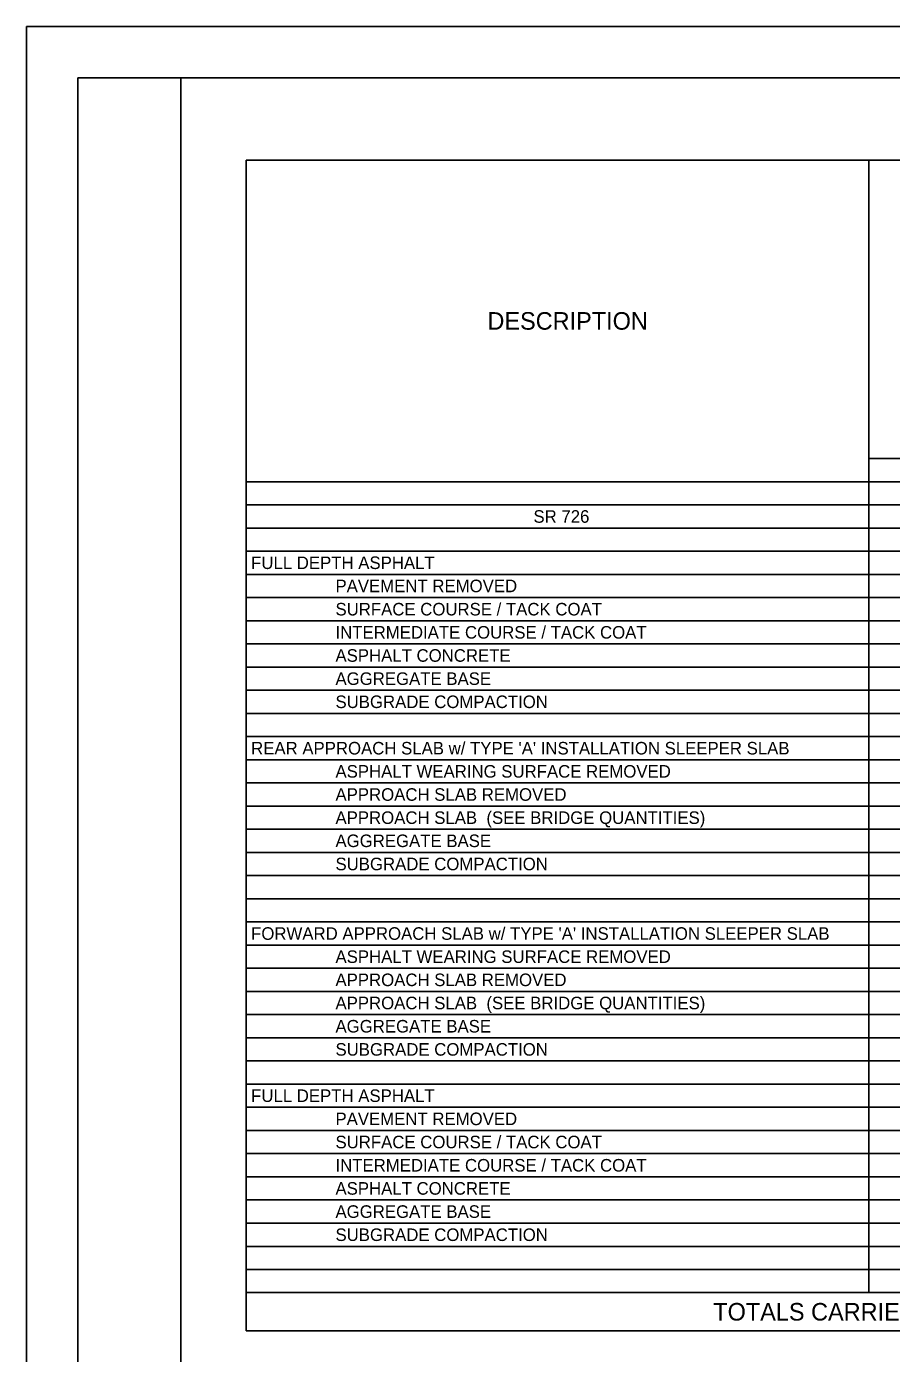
# Model space of a CAD drawing. Extents: x 0 to 34, y 0 to 22.
# Drawn here: x 0 to 8.41, y 9.11 to 22 of the extents above; entities that cross this region are included whole.
import ezdxf

# ---------------------------------------------------------------- set-up
doc = ezdxf.new("R2010")
doc.units = 0
for name, color, linetype in [('SH_Border', 7, 'Continuous'), ('SH_Cut_Line', 7, 'Continuous'), ('SH_Text', 7, 'Continuous')]:
    doc.layers.add(name, color=color, linetype=linetype)

msp = doc.modelspace()

# ---------------------------------------------------------------- linework, layer by layer
at = {"layer": 'SH_Border'}
for points in [[(0.5, 21.5), (1.5, 21.5), (1.5, 0.5), (0.5, 0.5)], [(1.5, 21.5), (33.5, 21.5), (33.5, 0.5), (1.5, 0.5)]]:
    msp.add_lwpolyline(points, close=True, dxfattribs=at)
at = {"layer": 'SH_Cut_Line'}
msp.add_lwpolyline([(0, 0), (34, 0), (34, 22), (0, 22)], close=True, dxfattribs=at)
at = {"layer": 'SH_Text'}
for p, q in [((2.135, 20.703), (22.576, 20.703)), ((2.135, 20.703), (2.135, 9.325)), ((8.186, 20.703), (8.186, 9.696)), ((8.186, 17.802), (22.576, 17.802)), ((2.135, 17.577), (22.576, 17.577)), ((2.135, 17.352), (22.576, 17.352)), ((2.135, 17.126), (22.576, 17.126)), ((2.135, 16.901), (22.576, 16.901)), ((2.135, 16.676), (22.576, 16.676)), ((2.135, 16.451), (22.576, 16.451)), ((2.135, 16.226), (22.576, 16.226)), ((2.135, 16.001), (22.576, 16.001)), ((2.135, 15.775), (22.576, 15.775)), ((2.135, 15.55), (22.576, 15.55)), ((2.135, 15.325), (22.576, 15.325)), ((2.135, 15.1), (22.576, 15.1)), ((2.135, 14.875), (22.576, 14.875)), ((2.135, 14.65), (22.576, 14.65)), ((2.135, 14.424), (22.576, 14.424)), ((2.135, 14.199), (22.576, 14.199)), ((2.135, 13.974), (22.576, 13.974)), ((2.135, 13.749), (22.576, 13.749)), ((2.135, 13.524), (22.576, 13.524)), ((2.135, 13.299), (22.576, 13.299)), ((2.135, 13.073), (22.576, 13.073)), ((2.135, 12.848), (22.576, 12.848)), ((2.135, 12.623), (22.576, 12.623)), ((2.135, 12.398), (22.576, 12.398)), ((2.135, 12.173), (22.576, 12.173)), ((2.135, 11.948), (22.576, 11.948)), ((2.135, 11.722), (22.576, 11.722)), ((2.135, 11.497), (22.576, 11.497)), ((2.135, 11.272), (22.576, 11.272)), ((2.135, 11.047), (22.576, 11.047)), ((2.135, 10.822), (22.576, 10.822)), ((2.135, 10.597), (22.576, 10.597)), ((2.135, 10.371), (22.576, 10.371)), ((2.135, 10.146), (22.576, 10.146)), ((2.135, 9.921), (22.576, 9.921)), ((2.135, 9.696), (22.576, 9.696)), ((2.135, 9.325), (22.576, 9.325))]:
    msp.add_line(p, q, dxfattribs=at)
for points in [[(2.135, 20.703), (2.954, 20.703), (2.954, 20.703), (2.135, 20.703)], [(2.135, 20.703), (7.367, 20.703), (7.367, 20.703), (2.135, 20.703)], [(2.135, 20.703), (3.284, 20.703), (3.284, 20.703), (2.135, 20.703)], [(2.135, 20.703), (3.284, 20.703), (3.284, 20.703), (2.135, 20.703)], [(2.135, 20.703), (3.1, 20.703), (3.1, 20.703), (2.135, 20.703)], [(2.135, 20.703), (3.1, 20.703), (3.1, 20.703), (2.135, 20.703)], [(2.135, 20.703), (3.1, 20.703), (3.1, 20.703), (2.135, 20.703)], [(2.135, 20.703), (3.1, 20.703), (3.1, 20.703), (2.135, 20.703)], [(2.135, 20.703), (3.1, 20.703), (3.1, 20.703), (2.135, 20.703)], [(2.135, 20.703), (2.868, 20.703), (2.868, 20.703), (2.135, 20.703)], [(2.135, 20.703), (2.868, 20.703), (2.868, 20.703), (2.135, 20.703)], [(2.135, 20.703), (2.868, 20.703), (2.868, 20.703), (2.135, 20.703)], [(2.135, 20.703), (2.868, 20.703), (2.868, 20.703), (2.135, 20.703)], [(2.135, 20.703), (3.052, 20.703), (3.052, 20.703), (2.135, 20.703)], [(2.135, 20.703), (2.905, 20.703), (2.905, 20.703), (2.135, 20.703)], [(2.135, 20.703), (2.893, 20.703), (2.893, 20.703), (2.135, 20.703)], [(2.135, 20.703), (3.1, 20.703), (3.1, 20.703), (2.135, 20.703)], [(2.135, 20.703), (3.052, 20.703), (3.052, 20.703), (2.135, 20.703)], [(2.135, 20.703), (2.954, 20.703), (2.954, 20.703), (2.135, 20.703)], [(2.135, 20.703), (7.367, 20.703), (7.367, 20.703), (2.135, 20.703)], [(2.135, 20.703), (3.284, 20.703), (3.284, 20.703), (2.135, 20.703)], [(2.135, 20.703), (3.284, 20.703), (3.284, 20.703), (2.135, 20.703)], [(2.135, 20.703), (3.1, 20.703), (3.1, 20.703), (2.135, 20.703)], [(2.135, 20.703), (3.1, 20.703), (3.1, 20.703), (2.135, 20.703)], [(2.135, 20.703), (3.1, 20.703), (3.1, 20.703), (2.135, 20.703)], [(2.135, 20.703), (3.1, 20.703), (3.1, 20.703), (2.135, 20.703)], [(2.135, 20.703), (3.1, 20.703), (3.1, 20.703), (2.135, 20.703)], [(2.135, 20.703), (2.868, 20.703), (2.868, 20.703), (2.135, 20.703)], [(2.135, 20.703), (2.868, 20.703), (2.868, 20.703), (2.135, 20.703)], [(2.135, 20.703), (2.868, 20.703), (2.868, 20.703), (2.135, 20.703)], [(2.135, 20.703), (2.868, 20.703), (2.868, 20.703), (2.135, 20.703)], [(2.135, 20.703), (3.052, 20.703), (3.052, 20.703), (2.135, 20.703)], [(2.135, 20.703), (2.905, 20.703), (2.905, 20.703), (2.135, 20.703)], [(2.135, 20.703), (2.893, 20.703), (2.893, 20.703), (2.135, 20.703)], [(2.135, 20.703), (3.1, 20.703), (3.1, 20.703), (2.135, 20.703)], [(2.135, 20.703), (3.052, 20.703), (3.052, 20.703), (2.135, 20.703)], [(2.135, 20.703), (2.954, 20.703), (2.954, 20.703), (2.135, 20.703)], [(2.135, 20.703), (7.367, 20.703), (7.367, 20.703), (2.135, 20.703)], [(2.135, 20.703), (3.284, 20.703), (3.284, 20.703), (2.135, 20.703)], [(2.135, 20.703), (3.284, 20.703), (3.284, 20.703), (2.135, 20.703)], [(2.135, 20.703), (3.1, 20.703), (3.1, 20.703), (2.135, 20.703)], [(2.135, 20.703), (3.1, 20.703), (3.1, 20.703), (2.135, 20.703)], [(2.135, 20.703), (3.1, 20.703), (3.1, 20.703), (2.135, 20.703)], [(2.135, 20.703), (3.1, 20.703), (3.1, 20.703), (2.135, 20.703)], [(2.135, 20.703), (3.1, 20.703), (3.1, 20.703), (2.135, 20.703)], [(2.135, 20.703), (2.868, 20.703), (2.868, 20.703), (2.135, 20.703)], [(2.135, 20.703), (2.868, 20.703), (2.868, 20.703), (2.135, 20.703)], [(2.135, 20.703), (2.868, 20.703), (2.868, 20.703), (2.135, 20.703)], [(2.135, 20.703), (2.868, 20.703), (2.868, 20.703), (2.135, 20.703)], [(2.135, 20.703), (3.052, 20.703), (3.052, 20.703), (2.135, 20.703)], [(2.135, 20.703), (2.905, 20.703), (2.905, 20.703), (2.135, 20.703)], [(2.135, 20.703), (2.893, 20.703), (2.893, 20.703), (2.135, 20.703)], [(2.135, 20.703), (3.1, 20.703), (3.1, 20.703), (2.135, 20.703)], [(2.135, 20.703), (3.052, 20.703), (3.052, 20.703), (2.135, 20.703)], [(2.135, 20.703), (2.954, 20.703), (2.954, 20.703), (2.135, 20.703)], [(2.135, 20.703), (7.367, 20.703), (7.367, 20.703), (2.135, 20.703)], [(2.135, 20.703), (3.284, 20.703), (3.284, 20.703), (2.135, 20.703)], [(2.135, 20.703), (3.284, 20.703), (3.284, 20.703), (2.135, 20.703)], [(2.135, 20.703), (3.1, 20.703), (3.1, 20.703), (2.135, 20.703)], [(2.135, 20.703), (3.1, 20.703), (3.1, 20.703), (2.135, 20.703)], [(2.135, 20.703), (3.1, 20.703), (3.1, 20.703), (2.135, 20.703)], [(2.135, 20.703), (3.1, 20.703), (3.1, 20.703), (2.135, 20.703)], [(2.135, 20.703), (3.1, 20.703), (3.1, 20.703), (2.135, 20.703)], [(2.135, 20.703), (2.868, 20.703), (2.868, 20.703), (2.135, 20.703)], [(2.135, 20.703), (2.868, 20.703), (2.868, 20.703), (2.135, 20.703)], [(2.135, 20.703), (2.868, 20.703), (2.868, 20.703), (2.135, 20.703)], [(2.135, 20.703), (2.868, 20.703), (2.868, 20.703), (2.135, 20.703)], [(2.135, 20.703), (3.052, 20.703), (3.052, 20.703), (2.135, 20.703)], [(2.135, 20.703), (2.905, 20.703), (2.905, 20.703), (2.135, 20.703)], [(2.135, 20.703), (2.893, 20.703), (2.893, 20.703), (2.135, 20.703)], [(2.135, 20.703), (3.1, 20.703), (3.1, 20.703), (2.135, 20.703)], [(2.135, 20.703), (3.052, 20.703), (3.052, 20.703), (2.135, 20.703)]]:
    msp.add_lwpolyline(points, close=True, dxfattribs=at)

# ---------------------------------------------------------------- texts
for s, height, p in [('DESCRIPTION', 0.1706, (4.48, 19.054)), ('SR 726', 0.1219, (4.927, 17.178)), ('FULL DEPTH ASPHALT', 0.12186, (2.183, 16.728)), ('PAVEMENT REMOVED', 0.12186, (3.003, 16.503)), ('SURFACE COURSE / TACK COAT', 0.12186, (3.003, 16.277)), ('INTERMEDIATE COURSE / TACK COAT', 0.12186, (3.003, 16.052)), ('ASPHALT CONCRETE', 0.12186, (3.003, 15.827)), ('AGGREGATE BASE', 0.12186, (3.003, 15.602)), ('SUBGRADE COMPACTION', 0.12186, (3.003, 15.377)), ("REAR APPROACH SLAB w/ TYPE 'A' INSTALLATION SLEEPER SLAB", 0.12186, (2.183, 14.926)), ('ASPHALT WEARING SURFACE REMOVED', 0.12186, (3.003, 14.701)), ('APPROACH SLAB REMOVED', 0.12186, (3.003, 14.476)), ('APPROACH SLAB  (SEE BRIDGE QUANTITIES)', 0.12186, (3.003, 14.251)), ('AGGREGATE BASE', 0.12186, (3.003, 14.026)), ('SUBGRADE COMPACTION', 0.12186, (3.003, 13.801)), ("FORWARD APPROACH SLAB w/ TYPE 'A' INSTALLATION SLEEPER SLAB", 0.12186, (2.183, 13.125)), ('ASPHALT WEARING SURFACE REMOVED', 0.12186, (3.003, 12.9)), ('APPROACH SLAB REMOVED', 0.12186, (3.003, 12.675)), ('APPROACH SLAB  (SEE BRIDGE QUANTITIES)', 0.12186, (3.003, 12.45)), ('AGGREGATE BASE', 0.12186, (3.003, 12.224)), ('SUBGRADE COMPACTION', 0.12186, (3.003, 11.999)), ('FULL DEPTH ASPHALT', 0.12186, (2.183, 11.549)), ('PAVEMENT REMOVED', 0.12186, (3.003, 11.324)), ('SURFACE COURSE / TACK COAT', 0.12186, (3.003, 11.099)), ('INTERMEDIATE COURSE / TACK COAT', 0.12186, (3.003, 10.873)), ('ASPHALT CONCRETE', 0.12186, (3.003, 10.648)), ('AGGREGATE BASE', 0.12186, (3.003, 10.423)), ('SUBGRADE COMPACTION', 0.12186, (3.003, 10.198)), ('TOTALS CARRIED TO GENERAL SUMMARY', 0.1706, (6.675, 9.425))]:
    msp.add_text(s, height=height, dxfattribs=at).set_placement(p)

doc.saveas('drawing.dxf')
